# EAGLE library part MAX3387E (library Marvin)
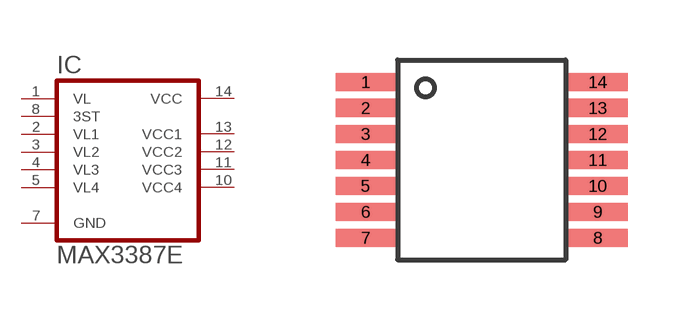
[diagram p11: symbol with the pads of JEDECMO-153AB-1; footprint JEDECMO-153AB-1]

Designator prefix IC

## MAX3387ES  [JEDECMO-153AB-1]
1  VL  pwr
2  VL1
3  VL2
4  VL3
5  VL4
7  GND  pwr
8  3ST  in
10  VCC4
11  VCC3
12  VCC2
13  VCC1
14  VCC  pwr

## Footprint JEDECMO-153AB-1 (pad centres in mm)
smd 1.5 x 0.45: 1 -2.9,1.95; 2 -2.9,1.3; 3 -2.9,0.65; 4 -2.9,0; 5 -2.9,-0.65; 6 -2.9,-1.3; 7 -2.9,-1.95; 8 2.9,-1.95; 9 2.9,-1.3; 10 2.9,-0.65; 11 2.9,0; 12 2.9,0.65; 13 2.9,1.3; 14 2.9,1.95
